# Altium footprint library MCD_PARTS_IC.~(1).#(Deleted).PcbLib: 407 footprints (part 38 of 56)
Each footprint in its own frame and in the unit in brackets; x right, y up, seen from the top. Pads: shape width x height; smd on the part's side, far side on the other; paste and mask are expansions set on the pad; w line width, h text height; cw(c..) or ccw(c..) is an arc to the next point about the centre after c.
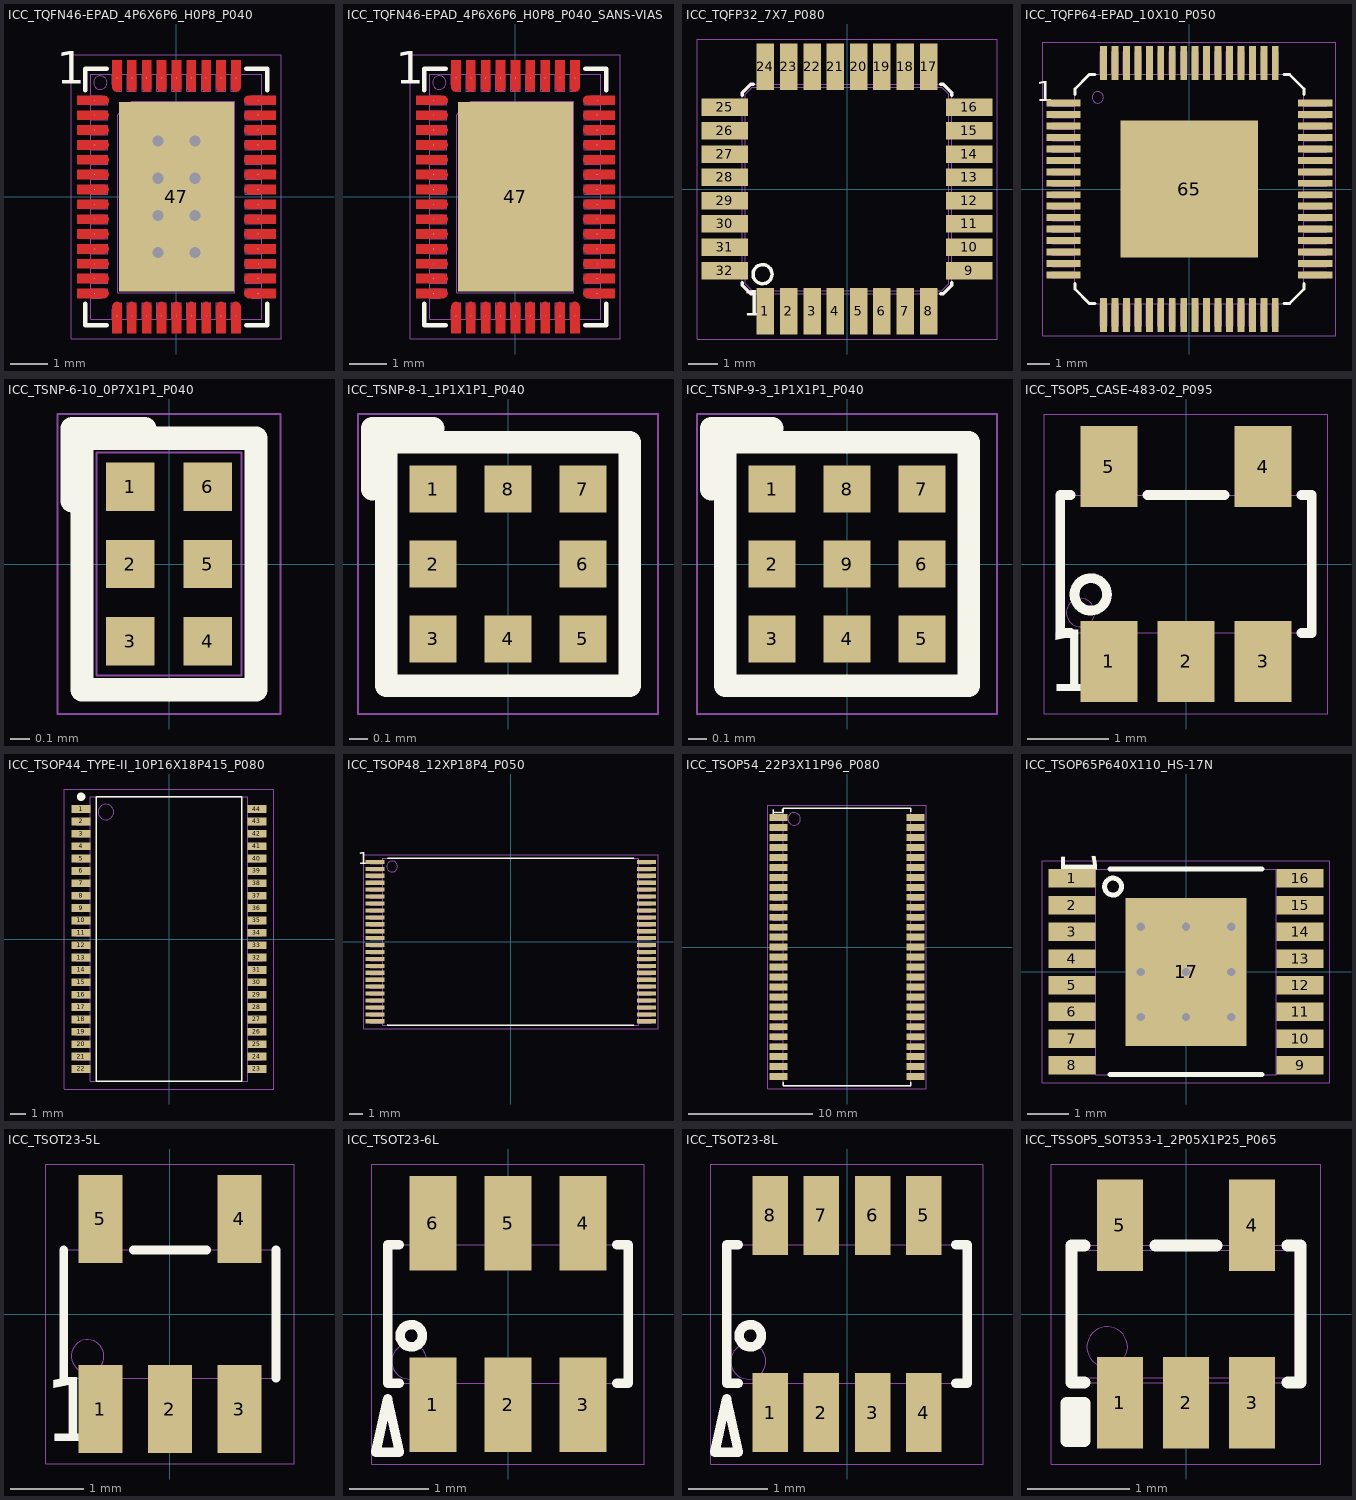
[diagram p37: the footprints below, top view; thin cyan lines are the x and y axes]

## ICC_TQFN46-EPAD_4P6X6P6_H0P8_P040 [mm]
height 0.8
pads (47):
  round 0.025 smd paste-2539.97 mask+0.035: 1(-2.2,2.6) 2(-2.2,2.2) 3(-2.2,1.8) 4(-2.2,1.4) 5(-2.2,1) 6(-2.2,0.6) 7(-2.2,0.2) 8(-2.2,-0.2) 9(-2.2,-0.6) 10(-2.2,-1) 11(-2.2,-1.4) 12(-2.2,-1.8) 13(-2.2,-2.2) 14(-2.2,-2.6) 15(-1.6,-3.2) 16(-1.2,-3.2) 17(-0.8,-3.2) 18(-0.4,-3.2) 19(0,-3.2) 20(0.4,-3.2) 21(0.8,-3.2) 22(1.2,-3.2) 23(1.6,-3.2) 24(2.2,-2.6) 25(2.2,-2.2) 26(2.2,-1.8) 27(2.2,-1.4) 28(2.2,-1) 29(2.2,-0.6) 30(2.2,-0.2) 31(2.2,0.2) 32(2.2,0.6) 33(2.2,1) 34(2.2,1.4) 35(2.2,1.8) 36(2.2,2.2) 37(2.2,2.6) 38(1.6,3.2) 39(1.2,3.2) 40(0.8,3.2) 41(0.4,3.2) 42(0,3.2) 43(-0.4,3.2) 44(-0.8,3.2) 45(-1.2,3.2) 46(-1.6,3.2)
  rect 3.1x5.1 smd paste-2539.97 mask+0.05: 47(0,0)
via 0.5,-1.5 diameter 0.55 hole 0.3
via 0.5,-0.5 diameter 0.55 hole 0.3
via -0.5,-1.5 diameter 0.55 hole 0.3
via -0.5,-0.5 diameter 0.55 hole 0.3
via -0.5,0.5 diameter 0.55 hole 0.3
via -0.5,1.5 diameter 0.55 hole 0.3
via 0.5,1.5 diameter 0.55 hole 0.3
via 0.5,0.5 diameter 0.55 hole 0.3
Top Layer:
  region: -1.6,2.825 -1.625,2.825 -1.671,2.844 -1.706,2.879 -1.725,2.925 -1.725,2.95 -1.725,3.675 -1.475,3.675 -1.475,2.95 -1.475,2.925 -1.494,2.879 -1.529,2.844 -1.575,2.825
  region: -1.2,2.825 -1.225,2.825 -1.271,2.844 -1.306,2.879 -1.325,2.925 -1.325,2.95 -1.325,3.675 -1.075,3.675 -1.075,2.95 -1.075,2.925 -1.094,2.879 -1.129,2.844 -1.175,2.825
  region: -0.8,2.825 -0.825,2.825 -0.871,2.844 -0.906,2.879 -0.925,2.925 -0.925,2.95 -0.925,3.675 -0.675,3.675 -0.675,2.95 -0.675,2.925 -0.694,2.879 -0.729,2.844 -0.775,2.825
  region: -0.4,2.825 -0.425,2.825 -0.471,2.844 -0.506,2.879 -0.525,2.925 -0.525,2.95 -0.525,3.675 -0.275,3.675 -0.275,2.95 -0.275,2.925 -0.294,2.879 -0.329,2.844 -0.375,2.825
  region: 0,2.825 -0.025,2.825 -0.071,2.844 -0.106,2.879 -0.125,2.925 -0.125,2.95 -0.125,3.675 0.125,3.675 0.125,2.95 0.125,2.925 0.106,2.879 0.071,2.844 0.025,2.825
  region: 0.4,2.825 0.375,2.825 0.329,2.844 0.294,2.879 0.275,2.925 0.275,2.95 0.275,3.675 0.525,3.675 0.525,2.95 0.525,2.925 0.506,2.879 0.471,2.844 0.425,2.825
  region: 1.6,2.825 1.625,2.825 1.671,2.844 1.706,2.879 1.725,2.925 1.725,2.95 1.725,3.675 1.475,3.675 1.475,2.95 1.475,2.925 1.494,2.879 1.529,2.844 1.575,2.825
  region: 0.8,2.825 0.775,2.825 0.729,2.844 0.694,2.879 0.675,2.925 0.675,2.95 0.675,3.675 0.925,3.675 0.925,2.95 0.925,2.925 0.906,2.879 0.871,2.844 0.825,2.825
  region: 1.2,2.825 1.175,2.825 1.129,2.844 1.094,2.879 1.075,2.925 1.075,2.95 1.075,3.675 1.325,3.675 1.325,2.95 1.325,2.925 1.306,2.879 1.271,2.844 1.225,2.825
  region: 1.6,-2.825 1.625,-2.825 1.671,-2.844 1.706,-2.879 1.725,-2.925 1.725,-2.95 1.725,-3.675 1.475,-3.675 1.475,-2.95 1.475,-2.925 1.494,-2.879 1.529,-2.844 1.575,-2.825
  region: 1.2,-2.825 1.225,-2.825 1.271,-2.844 1.306,-2.879 1.325,-2.925 1.325,-2.95 1.325,-3.675 1.075,-3.675 1.075,-2.95 1.075,-2.925 1.094,-2.879 1.129,-2.844 1.175,-2.825
  region: 0.8,-2.825 0.825,-2.825 0.871,-2.844 0.906,-2.879 0.925,-2.925 0.925,-2.95 0.925,-3.675 0.675,-3.675 0.675,-2.95 0.675,-2.925 0.694,-2.879 0.729,-2.844 0.775,-2.825
  region: 0.4,-2.825 0.425,-2.825 0.471,-2.844 0.506,-2.879 0.525,-2.925 0.525,-2.95 0.525,-3.675 0.275,-3.675 0.275,-2.95 0.275,-2.925 0.294,-2.879 0.329,-2.844 0.375,-2.825
  region: 0,-2.825 0.025,-2.825 0.071,-2.844 0.106,-2.879 0.125,-2.925 0.125,-2.95 0.125,-3.675 -0.125,-3.675 -0.125,-2.95 -0.125,-2.925 -0.106,-2.879 -0.071,-2.844 -0.025,-2.825
  region: -0.4,-2.825 -0.375,-2.825 -0.329,-2.844 -0.294,-2.879 -0.275,-2.925 -0.275,-2.95 -0.275,-3.675 -0.525,-3.675 -0.525,-2.95 -0.525,-2.925 -0.506,-2.879 -0.471,-2.844 -0.425,-2.825
  region: -1.6,-2.825 -1.625,-2.825 -1.671,-2.844 -1.706,-2.879 -1.725,-2.925 -1.725,-2.95 -1.725,-3.675 -1.475,-3.675 -1.475,-2.95 -1.475,-2.925 -1.494,-2.879 -1.529,-2.844 -1.575,-2.825
  region: -0.8,-2.825 -0.775,-2.825 -0.729,-2.844 -0.694,-2.879 -0.675,-2.925 -0.675,-2.95 -0.675,-3.675 -0.925,-3.675 -0.925,-2.95 -0.925,-2.925 -0.906,-2.879 -0.871,-2.844 -0.825,-2.825
  region: -1.2,-2.825 -1.175,-2.825 -1.129,-2.844 -1.094,-2.879 -1.075,-2.925 -1.075,-2.95 -1.075,-3.675 -1.325,-3.675 -1.325,-2.95 -1.325,-2.925 -1.306,-2.879 -1.271,-2.844 -1.225,-2.825
  region: 1.825,-2.6 1.825,-2.625 1.844,-2.671 1.879,-2.706 1.925,-2.725 1.95,-2.725 2.675,-2.725 2.675,-2.475 1.95,-2.475 1.925,-2.475 1.879,-2.494 1.844,-2.529 1.825,-2.575
  region: 1.825,-2.2 1.825,-2.225 1.844,-2.271 1.879,-2.306 1.925,-2.325 1.95,-2.325 2.675,-2.325 2.675,-2.075 1.95,-2.075 1.925,-2.075 1.879,-2.094 1.844,-2.129 1.825,-2.175
  region: 1.825,-1.8 1.825,-1.825 1.844,-1.871 1.879,-1.906 1.925,-1.925 1.95,-1.925 2.675,-1.925 2.675,-1.675 1.95,-1.675 1.925,-1.675 1.879,-1.694 1.844,-1.729 1.825,-1.775
  region: 1.825,-1.4 1.825,-1.425 1.844,-1.471 1.879,-1.506 1.925,-1.525 1.95,-1.525 2.675,-1.525 2.675,-1.275 1.95,-1.275 1.925,-1.275 1.879,-1.294 1.844,-1.329 1.825,-1.375
  region: 1.825,-1 1.825,-1.025 1.844,-1.071 1.879,-1.106 1.925,-1.125 1.95,-1.125 2.675,-1.125 2.675,-0.875 1.95,-0.875 1.925,-0.875 1.879,-0.894 1.844,-0.929 1.825,-0.975
  region: 1.825,-0.6 1.825,-0.625 1.844,-0.671 1.879,-0.706 1.925,-0.725 1.95,-0.725 2.675,-0.725 2.675,-0.475 1.95,-0.475 1.925,-0.475 1.879,-0.494 1.844,-0.529 1.825,-0.575
  region: 1.825,-0.2 1.825,-0.225 1.844,-0.271 1.879,-0.306 1.925,-0.325 1.95,-0.325 2.675,-0.325 2.675,-0.075 1.95,-0.075 1.925,-0.075 1.879,-0.094 1.844,-0.129 1.825,-0.175
  region: 1.825,0.2 1.825,0.175 1.844,0.129 1.879,0.094 1.925,0.075 1.95,0.075 2.675,0.075 2.675,0.325 1.95,0.325 1.925,0.325 1.879,0.306 1.844,0.271 1.825,0.225
  region: 1.825,0.6 1.825,0.575 1.844,0.529 1.879,0.494 1.925,0.475 1.95,0.475 2.675,0.475 2.675,0.725 1.95,0.725 1.925,0.725 1.879,0.706 1.844,0.671 1.825,0.625
  region: 1.825,1 1.825,0.975 1.844,0.929 1.879,0.894 1.925,0.875 1.95,0.875 2.675,0.875 2.675,1.125 1.95,1.125 1.925,1.125 1.879,1.106 1.844,1.071 1.825,1.025
  region: 1.825,1.4 1.825,1.375 1.844,1.329 1.879,1.294 1.925,1.275 1.95,1.275 2.675,1.275 2.675,1.525 1.95,1.525 1.925,1.525 1.879,1.506 1.844,1.471 1.825,1.425
  region: 1.825,2.6 1.825,2.575 1.844,2.529 1.879,2.494 1.925,2.475 1.95,2.475 2.675,2.475 2.675,2.725 1.95,2.725 1.925,2.725 1.879,2.706 1.844,2.671 1.825,2.625
  region: 1.825,1.8 1.825,1.775 1.844,1.729 1.879,1.694 1.925,1.675 1.95,1.675 2.675,1.675 2.675,1.925 1.95,1.925 1.925,1.925 1.879,1.906 1.844,1.871 1.825,1.825
  region: 1.825,2.2 1.825,2.175 1.844,2.129 1.879,2.094 1.925,2.075 1.95,2.075 2.675,2.075 2.675,2.325 1.95,2.325 1.925,2.325 1.879,2.306 1.844,2.271 1.825,2.225
  region: -1.825,-2.6 -1.825,-2.625 -1.844,-2.671 -1.879,-2.706 -1.925,-2.725 -1.95,-2.725 -2.675,-2.725 -2.675,-2.475 -1.95,-2.475 -1.925,-2.475 -1.879,-2.494 -1.844,-2.529 -1.825,-2.575
  region: -1.825,-2.2 -1.825,-2.225 -1.844,-2.271 -1.879,-2.306 -1.925,-2.325 -1.95,-2.325 -2.675,-2.325 -2.675,-2.075 -1.95,-2.075 -1.925,-2.075 -1.879,-2.094 -1.844,-2.129 -1.825,-2.175
  region: -1.825,-1.8 -1.825,-1.825 -1.844,-1.871 -1.879,-1.906 -1.925,-1.925 -1.95,-1.925 -2.675,-1.925 -2.675,-1.675 -1.95,-1.675 -1.925,-1.675 -1.879,-1.694 -1.844,-1.729 -1.825,-1.775
  region: -1.825,-1.4 -1.825,-1.425 -1.844,-1.471 -1.879,-1.506 -1.925,-1.525 -1.95,-1.525 -2.675,-1.525 -2.675,-1.275 -1.95,-1.275 -1.925,-1.275 -1.879,-1.294 -1.844,-1.329 -1.825,-1.375
  region: -1.825,-1 -1.825,-1.025 -1.844,-1.071 -1.879,-1.106 -1.925,-1.125 -1.95,-1.125 -2.675,-1.125 -2.675,-0.875 -1.95,-0.875 -1.925,-0.875 -1.879,-0.894 -1.844,-0.929 -1.825,-0.975
  region: -1.825,-0.6 -1.825,-0.625 -1.844,-0.671 -1.879,-0.706 -1.925,-0.725 -1.95,-0.725 -2.675,-0.725 -2.675,-0.475 -1.95,-0.475 -1.925,-0.475 -1.879,-0.494 -1.844,-0.529 -1.825,-0.575
  region: -1.825,-0.2 -1.825,-0.225 -1.844,-0.271 -1.879,-0.306 -1.925,-0.325 -1.95,-0.325 -2.675,-0.325 -2.675,-0.075 -1.95,-0.075 -1.925,-0.075 -1.879,-0.094 -1.844,-0.129 -1.825,-0.175
  region: -1.825,0.2 -1.825,0.175 -1.844,0.129 -1.879,0.094 -1.925,0.075 -1.95,0.075 -2.675,0.075 -2.675,0.325 -1.95,0.325 -1.925,0.325 -1.879,0.306 -1.844,0.271 -1.825,0.225
  region: -1.825,0.6 -1.825,0.575 -1.844,0.529 -1.879,0.494 -1.925,0.475 -1.95,0.475 -2.675,0.475 -2.675,0.725 -1.95,0.725 -1.925,0.725 -1.879,0.706 -1.844,0.671 -1.825,0.625
  region: -1.825,1 -1.825,0.975 -1.844,0.929 -1.879,0.894 -1.925,0.875 -1.95,0.875 -2.675,0.875 -2.675,1.125 -1.95,1.125 -1.925,1.125 -1.879,1.106 -1.844,1.071 -1.825,1.025
  region: -1.825,1.4 -1.825,1.375 -1.844,1.329 -1.879,1.294 -1.925,1.275 -1.95,1.275 -2.675,1.275 -2.675,1.525 -1.95,1.525 -1.925,1.525 -1.879,1.506 -1.844,1.471 -1.825,1.425
  region: -1.825,2.6 -1.825,2.575 -1.844,2.529 -1.879,2.494 -1.925,2.475 -1.95,2.475 -2.675,2.475 -2.675,2.725 -1.95,2.725 -1.925,2.725 -1.879,2.706 -1.844,2.671 -1.825,2.625
  region: -1.825,1.8 -1.825,1.775 -1.844,1.729 -1.879,1.694 -1.925,1.675 -1.95,1.675 -2.675,1.675 -2.675,1.925 -1.95,1.925 -1.925,1.925 -1.879,1.906 -1.844,1.871 -1.825,1.825
  region: -1.825,2.2 -1.825,2.175 -1.844,2.129 -1.879,2.094 -1.925,2.075 -1.95,2.075 -2.675,2.075 -2.675,2.325 -1.95,2.325 -1.925,2.325 -1.879,2.306 -1.844,2.271 -1.825,2.225
Top Overlay:
  lines w0.12: -2.45,-2.875 -2.45,-3.45 -1.875,-3.45 ; -2.45,2.875 -2.45,3.45 -1.875,3.45 ; 1.875,-3.45 2.45,-3.45 2.45,-2.875 ; 1.875,3.45 2.45,3.45 2.45,2.875
  text "1" at -3.225,2.75 h1.5
Top Paste:
  drawing of 52 lines, arcs and shapes, not listed
M14-Top Assembly:
  drawing of 164 lines, arcs and shapes, not listed
  text "'.Designator'" at -2,-0.5 h0.75
M16-Top Courtyard:
  lines w0.01: -2.825,-3.825 2.825,-3.825 2.825,3.825 -2.825,3.825 -2.825,-3.825
3D body: height 0.8, standoff 0, extent -2.3,-3.3 2.3,3.3
3D body: height 0.81, standoff 0.8, extent -2.006,2.616 -1.606,3.016

## ICC_TQFN46-EPAD_4P6X6P6_H0P8_P040_SANS-VIAS [mm]
height 0.8
pads (47):
  round 0.025 smd paste-2539.97 mask+0.035: 1(-2.2,2.6) 2(-2.2,2.2) 3(-2.2,1.8) 4(-2.2,1.4) 5(-2.2,1) 6(-2.2,0.6) 7(-2.2,0.2) 8(-2.2,-0.2) 9(-2.2,-0.6) 10(-2.2,-1) 11(-2.2,-1.4) 12(-2.2,-1.8) 13(-2.2,-2.2) 14(-2.2,-2.6) 15(-1.6,-3.2) 16(-1.2,-3.2) 17(-0.8,-3.2) 18(-0.4,-3.2) 19(0,-3.2) 20(0.4,-3.2) 21(0.8,-3.2) 22(1.2,-3.2) 23(1.6,-3.2) 24(2.2,-2.6) 25(2.2,-2.2) 26(2.2,-1.8) 27(2.2,-1.4) 28(2.2,-1) 29(2.2,-0.6) 30(2.2,-0.2) 31(2.2,0.2) 32(2.2,0.6) 33(2.2,1) 34(2.2,1.4) 35(2.2,1.8) 36(2.2,2.2) 37(2.2,2.6) 38(1.6,3.2) 39(1.2,3.2) 40(0.8,3.2) 41(0.4,3.2) 42(0,3.2) 43(-0.4,3.2) 44(-0.8,3.2) 45(-1.2,3.2) 46(-1.6,3.2)
  rect 3.1x5.1 smd paste-2539.97 mask+0.05: 47(0,0)
Top Layer:
  region: -1.825,2.2 -1.825,2.175 -1.844,2.129 -1.879,2.094 -1.925,2.075 -1.95,2.075 -2.675,2.075 -2.675,2.325 -1.95,2.325 -1.925,2.325 -1.879,2.306 -1.844,2.271 -1.825,2.225
  region: -1.825,1.8 -1.825,1.775 -1.844,1.729 -1.879,1.694 -1.925,1.675 -1.95,1.675 -2.675,1.675 -2.675,1.925 -1.95,1.925 -1.925,1.925 -1.879,1.906 -1.844,1.871 -1.825,1.825
  region: -1.825,2.6 -1.825,2.575 -1.844,2.529 -1.879,2.494 -1.925,2.475 -1.95,2.475 -2.675,2.475 -2.675,2.725 -1.95,2.725 -1.925,2.725 -1.879,2.706 -1.844,2.671 -1.825,2.625
  region: -1.825,1.4 -1.825,1.375 -1.844,1.329 -1.879,1.294 -1.925,1.275 -1.95,1.275 -2.675,1.275 -2.675,1.525 -1.95,1.525 -1.925,1.525 -1.879,1.506 -1.844,1.471 -1.825,1.425
  region: -1.825,1 -1.825,0.975 -1.844,0.929 -1.879,0.894 -1.925,0.875 -1.95,0.875 -2.675,0.875 -2.675,1.125 -1.95,1.125 -1.925,1.125 -1.879,1.106 -1.844,1.071 -1.825,1.025
  region: -1.825,0.6 -1.825,0.575 -1.844,0.529 -1.879,0.494 -1.925,0.475 -1.95,0.475 -2.675,0.475 -2.675,0.725 -1.95,0.725 -1.925,0.725 -1.879,0.706 -1.844,0.671 -1.825,0.625
  region: -1.825,0.2 -1.825,0.175 -1.844,0.129 -1.879,0.094 -1.925,0.075 -1.95,0.075 -2.675,0.075 -2.675,0.325 -1.95,0.325 -1.925,0.325 -1.879,0.306 -1.844,0.271 -1.825,0.225
  region: -1.825,-0.2 -1.825,-0.225 -1.844,-0.271 -1.879,-0.306 -1.925,-0.325 -1.95,-0.325 -2.675,-0.325 -2.675,-0.075 -1.95,-0.075 -1.925,-0.075 -1.879,-0.094 -1.844,-0.129 -1.825,-0.175
  region: -1.825,-0.6 -1.825,-0.625 -1.844,-0.671 -1.879,-0.706 -1.925,-0.725 -1.95,-0.725 -2.675,-0.725 -2.675,-0.475 -1.95,-0.475 -1.925,-0.475 -1.879,-0.494 -1.844,-0.529 -1.825,-0.575
  region: -1.825,-1 -1.825,-1.025 -1.844,-1.071 -1.879,-1.106 -1.925,-1.125 -1.95,-1.125 -2.675,-1.125 -2.675,-0.875 -1.95,-0.875 -1.925,-0.875 -1.879,-0.894 -1.844,-0.929 -1.825,-0.975
  region: -1.825,-1.4 -1.825,-1.425 -1.844,-1.471 -1.879,-1.506 -1.925,-1.525 -1.95,-1.525 -2.675,-1.525 -2.675,-1.275 -1.95,-1.275 -1.925,-1.275 -1.879,-1.294 -1.844,-1.329 -1.825,-1.375
  region: -1.825,-1.8 -1.825,-1.825 -1.844,-1.871 -1.879,-1.906 -1.925,-1.925 -1.95,-1.925 -2.675,-1.925 -2.675,-1.675 -1.95,-1.675 -1.925,-1.675 -1.879,-1.694 -1.844,-1.729 -1.825,-1.775
  region: -1.825,-2.2 -1.825,-2.225 -1.844,-2.271 -1.879,-2.306 -1.925,-2.325 -1.95,-2.325 -2.675,-2.325 -2.675,-2.075 -1.95,-2.075 -1.925,-2.075 -1.879,-2.094 -1.844,-2.129 -1.825,-2.175
  region: -1.825,-2.6 -1.825,-2.625 -1.844,-2.671 -1.879,-2.706 -1.925,-2.725 -1.95,-2.725 -2.675,-2.725 -2.675,-2.475 -1.95,-2.475 -1.925,-2.475 -1.879,-2.494 -1.844,-2.529 -1.825,-2.575
  region: 1.825,2.2 1.825,2.175 1.844,2.129 1.879,2.094 1.925,2.075 1.95,2.075 2.675,2.075 2.675,2.325 1.95,2.325 1.925,2.325 1.879,2.306 1.844,2.271 1.825,2.225
  region: 1.825,1.8 1.825,1.775 1.844,1.729 1.879,1.694 1.925,1.675 1.95,1.675 2.675,1.675 2.675,1.925 1.95,1.925 1.925,1.925 1.879,1.906 1.844,1.871 1.825,1.825
  region: 1.825,2.6 1.825,2.575 1.844,2.529 1.879,2.494 1.925,2.475 1.95,2.475 2.675,2.475 2.675,2.725 1.95,2.725 1.925,2.725 1.879,2.706 1.844,2.671 1.825,2.625
  region: 1.825,1.4 1.825,1.375 1.844,1.329 1.879,1.294 1.925,1.275 1.95,1.275 2.675,1.275 2.675,1.525 1.95,1.525 1.925,1.525 1.879,1.506 1.844,1.471 1.825,1.425
  region: 1.825,1 1.825,0.975 1.844,0.929 1.879,0.894 1.925,0.875 1.95,0.875 2.675,0.875 2.675,1.125 1.95,1.125 1.925,1.125 1.879,1.106 1.844,1.071 1.825,1.025
  region: 1.825,0.6 1.825,0.575 1.844,0.529 1.879,0.494 1.925,0.475 1.95,0.475 2.675,0.475 2.675,0.725 1.95,0.725 1.925,0.725 1.879,0.706 1.844,0.671 1.825,0.625
  region: 1.825,0.2 1.825,0.175 1.844,0.129 1.879,0.094 1.925,0.075 1.95,0.075 2.675,0.075 2.675,0.325 1.95,0.325 1.925,0.325 1.879,0.306 1.844,0.271 1.825,0.225
  region: 1.825,-0.2 1.825,-0.225 1.844,-0.271 1.879,-0.306 1.925,-0.325 1.95,-0.325 2.675,-0.325 2.675,-0.075 1.95,-0.075 1.925,-0.075 1.879,-0.094 1.844,-0.129 1.825,-0.175
  region: 1.825,-0.6 1.825,-0.625 1.844,-0.671 1.879,-0.706 1.925,-0.725 1.95,-0.725 2.675,-0.725 2.675,-0.475 1.95,-0.475 1.925,-0.475 1.879,-0.494 1.844,-0.529 1.825,-0.575
  region: 1.825,-1 1.825,-1.025 1.844,-1.071 1.879,-1.106 1.925,-1.125 1.95,-1.125 2.675,-1.125 2.675,-0.875 1.95,-0.875 1.925,-0.875 1.879,-0.894 1.844,-0.929 1.825,-0.975
  region: 1.825,-1.4 1.825,-1.425 1.844,-1.471 1.879,-1.506 1.925,-1.525 1.95,-1.525 2.675,-1.525 2.675,-1.275 1.95,-1.275 1.925,-1.275 1.879,-1.294 1.844,-1.329 1.825,-1.375
  region: 1.825,-1.8 1.825,-1.825 1.844,-1.871 1.879,-1.906 1.925,-1.925 1.95,-1.925 2.675,-1.925 2.675,-1.675 1.95,-1.675 1.925,-1.675 1.879,-1.694 1.844,-1.729 1.825,-1.775
  region: 1.825,-2.2 1.825,-2.225 1.844,-2.271 1.879,-2.306 1.925,-2.325 1.95,-2.325 2.675,-2.325 2.675,-2.075 1.95,-2.075 1.925,-2.075 1.879,-2.094 1.844,-2.129 1.825,-2.175
  region: 1.825,-2.6 1.825,-2.625 1.844,-2.671 1.879,-2.706 1.925,-2.725 1.95,-2.725 2.675,-2.725 2.675,-2.475 1.95,-2.475 1.925,-2.475 1.879,-2.494 1.844,-2.529 1.825,-2.575
  region: -1.2,-2.825 -1.175,-2.825 -1.129,-2.844 -1.094,-2.879 -1.075,-2.925 -1.075,-2.95 -1.075,-3.675 -1.325,-3.675 -1.325,-2.95 -1.325,-2.925 -1.306,-2.879 -1.271,-2.844 -1.225,-2.825
  region: -0.8,-2.825 -0.775,-2.825 -0.729,-2.844 -0.694,-2.879 -0.675,-2.925 -0.675,-2.95 -0.675,-3.675 -0.925,-3.675 -0.925,-2.95 -0.925,-2.925 -0.906,-2.879 -0.871,-2.844 -0.825,-2.825
  region: -1.6,-2.825 -1.625,-2.825 -1.671,-2.844 -1.706,-2.879 -1.725,-2.925 -1.725,-2.95 -1.725,-3.675 -1.475,-3.675 -1.475,-2.95 -1.475,-2.925 -1.494,-2.879 -1.529,-2.844 -1.575,-2.825
  region: -0.4,-2.825 -0.375,-2.825 -0.329,-2.844 -0.294,-2.879 -0.275,-2.925 -0.275,-2.95 -0.275,-3.675 -0.525,-3.675 -0.525,-2.95 -0.525,-2.925 -0.506,-2.879 -0.471,-2.844 -0.425,-2.825
  region: 0,-2.825 0.025,-2.825 0.071,-2.844 0.106,-2.879 0.125,-2.925 0.125,-2.95 0.125,-3.675 -0.125,-3.675 -0.125,-2.95 -0.125,-2.925 -0.106,-2.879 -0.071,-2.844 -0.025,-2.825
  region: 0.4,-2.825 0.425,-2.825 0.471,-2.844 0.506,-2.879 0.525,-2.925 0.525,-2.95 0.525,-3.675 0.275,-3.675 0.275,-2.95 0.275,-2.925 0.294,-2.879 0.329,-2.844 0.375,-2.825
  region: 0.8,-2.825 0.825,-2.825 0.871,-2.844 0.906,-2.879 0.925,-2.925 0.925,-2.95 0.925,-3.675 0.675,-3.675 0.675,-2.95 0.675,-2.925 0.694,-2.879 0.729,-2.844 0.775,-2.825
  region: 1.2,-2.825 1.225,-2.825 1.271,-2.844 1.306,-2.879 1.325,-2.925 1.325,-2.95 1.325,-3.675 1.075,-3.675 1.075,-2.95 1.075,-2.925 1.094,-2.879 1.129,-2.844 1.175,-2.825
  region: 1.6,-2.825 1.625,-2.825 1.671,-2.844 1.706,-2.879 1.725,-2.925 1.725,-2.95 1.725,-3.675 1.475,-3.675 1.475,-2.95 1.475,-2.925 1.494,-2.879 1.529,-2.844 1.575,-2.825
  region: 1.2,2.825 1.175,2.825 1.129,2.844 1.094,2.879 1.075,2.925 1.075,2.95 1.075,3.675 1.325,3.675 1.325,2.95 1.325,2.925 1.306,2.879 1.271,2.844 1.225,2.825
  region: 0.8,2.825 0.775,2.825 0.729,2.844 0.694,2.879 0.675,2.925 0.675,2.95 0.675,3.675 0.925,3.675 0.925,2.95 0.925,2.925 0.906,2.879 0.871,2.844 0.825,2.825
  region: 1.6,2.825 1.625,2.825 1.671,2.844 1.706,2.879 1.725,2.925 1.725,2.95 1.725,3.675 1.475,3.675 1.475,2.95 1.475,2.925 1.494,2.879 1.529,2.844 1.575,2.825
  region: 0.4,2.825 0.375,2.825 0.329,2.844 0.294,2.879 0.275,2.925 0.275,2.95 0.275,3.675 0.525,3.675 0.525,2.95 0.525,2.925 0.506,2.879 0.471,2.844 0.425,2.825
  region: 0,2.825 -0.025,2.825 -0.071,2.844 -0.106,2.879 -0.125,2.925 -0.125,2.95 -0.125,3.675 0.125,3.675 0.125,2.95 0.125,2.925 0.106,2.879 0.071,2.844 0.025,2.825
  region: -0.4,2.825 -0.425,2.825 -0.471,2.844 -0.506,2.879 -0.525,2.925 -0.525,2.95 -0.525,3.675 -0.275,3.675 -0.275,2.95 -0.275,2.925 -0.294,2.879 -0.329,2.844 -0.375,2.825
  region: -0.8,2.825 -0.825,2.825 -0.871,2.844 -0.906,2.879 -0.925,2.925 -0.925,2.95 -0.925,3.675 -0.675,3.675 -0.675,2.95 -0.675,2.925 -0.694,2.879 -0.729,2.844 -0.775,2.825
  region: -1.2,2.825 -1.225,2.825 -1.271,2.844 -1.306,2.879 -1.325,2.925 -1.325,2.95 -1.325,3.675 -1.075,3.675 -1.075,2.95 -1.075,2.925 -1.094,2.879 -1.129,2.844 -1.175,2.825
  region: -1.6,2.825 -1.625,2.825 -1.671,2.844 -1.706,2.879 -1.725,2.925 -1.725,2.95 -1.725,3.675 -1.475,3.675 -1.475,2.95 -1.475,2.925 -1.494,2.879 -1.529,2.844 -1.575,2.825
Top Overlay:
  lines w0.12: -2.45,-2.875 -2.45,-3.45 -1.875,-3.45 ; -2.45,2.875 -2.45,3.45 -1.875,3.45 ; 1.875,-3.45 2.45,-3.45 2.45,-2.875 ; 1.875,3.45 2.45,3.45 2.45,2.875
  text "1" at -3.225,2.75 h1.5
Top Paste:
  drawing of 52 lines, arcs and shapes, not listed
M14-Top Assembly:
  drawing of 164 lines, arcs and shapes, not listed
  text "'.Designator'" at -2,-0.5 h0.75
M16-Top Courtyard:
  lines w0.01: -2.825,-3.825 -2.825,3.825 2.825,3.825 2.825,-3.825 -2.825,-3.825
3D body: height 0.81, standoff 0.8, extent -2.006,2.616 -1.606,3.016
3D body: height 0.8, standoff 0, extent -2.3,-3.3 2.3,3.3

## ICC_TQFP32_7X7_P080 [mm] "MCD-01846"
height 1.6
pads (32):
  rect 0.6x1.6 smd mask+0.05: 1(-2.8,-4.2) 2(-2,-4.2) 3(-1.2,-4.2) 4(-0.4,-4.2) 5(0.4,-4.2) 6(1.2,-4.2) 7(2,-4.2) 8(2.8,-4.2) 17(2.8,4.2) 18(2,4.2) 19(1.2,4.2) 20(0.4,4.2) 21(-0.4,4.2) 22(-1.2,4.2) 23(-2,4.2) 24(-2.8,4.2)
  rect 1.6x0.6 smd mask+0.05: 9(4.2,-2.8) 10(4.2,-2) 11(4.2,-1.2) 12(4.2,-0.4) 13(4.2,0.4) 14(4.2,1.2) 15(4.2,2) 16(4.2,2.8) 25(-4.2,2.8) 26(-4.2,2) 27(-4.2,1.2) 28(-4.2,0.4) 29(-4.2,-0.4) 30(-4.2,-1.2) 31(-4.2,-2) 32(-4.2,-2.8)
Top Overlay:
  circle w0.12: c-2.9,-2.925 r0.326
  lines w0.12: -3.6,-3.225 -3.6,-3.3 -3.3,-3.6 -3.225,-3.6 ; -3.6,3.225 -3.6,3.3 -3.3,3.6 -3.225,3.6 ; 3.225,-3.6 3.3,-3.6 3.6,-3.3 3.6,-3.225 ; 3.225,3.6 3.3,3.6 3.6,3.3 3.6,3.225
  text "1" at -3.575,-4.65 h1.5
M14-Top Assembly:
  circle w0.01: c-2.9,-2.925 r0.335
  lines w0.01: -3.6,-3 -4.6,-3 -4.6,-2.6 -3.6,-2.6 ; -3.6,-2.2 -4.6,-2.2 -4.6,-1.8 -3.6,-1.8 ; -3.6,-1.4 -4.6,-1.4 -4.6,-1 -3.6,-1 ; -3.6,-0.6 -4.6,-0.6 -4.6,-0.2 -3.6,-0.2 ; -3.6,0.2 -4.6,0.2 -4.6,0.6 -3.6,0.6 ; -3.6,1 -4.6,1 -4.6,1.4 -3.6,1.4 ; -3.6,1.8 -4.6,1.8 -4.6,2.2 -3.6,2.2 ; -3.6,2.6 -4.6,2.6 -4.6,3 -3.6,3 ; -3,-3.6 -3,-4.6 -2.6,-4.6 -2.6,-3.6 ; -3,3.6 -3,4.6 -2.6,4.6 -2.6,3.6 ; -2.2,-3.6 -2.2,-4.6 -1.8,-4.6 -1.8,-3.6 ; -2.2,3.6 -2.2,4.6 -1.8,4.6 -1.8,3.6 ; -1.4,-3.6 -1.4,-4.6 -1,-4.6 -1,-3.6 ; -1.4,3.6 -1.4,4.6 -1,4.6 -1,3.6 ; -0.6,-3.6 -0.6,-4.6 -0.2,-4.6 -0.2,-3.6 ; -0.6,3.6 -0.6,4.6 -0.2,4.6 -0.2,3.6 ; 0.2,-3.6 0.2,-4.6 0.6,-4.6 0.6,-3.6 ; 0.2,3.6 0.2,4.6 0.6,4.6 0.6,3.6 ; 1,-3.6 1,-4.6 1.4,-4.6 1.4,-3.6 ; 1,3.6 1,4.6 1.4,4.6 1.4,3.6 ; 1.8,-3.6 1.8,-4.6 2.2,-4.6 2.2,-3.6 ; 1.8,3.6 1.8,4.6 2.2,4.6 2.2,3.6 ; 2.6,-3.6 2.6,-4.6 3,-4.6 3,-3.6 ; 2.6,3.6 2.6,4.6 3,4.6 3,3.6 ; 3.6,-3 4.6,-3 4.6,-2.6 3.6,-2.6 ; 3.6,-2.2 4.6,-2.2 4.6,-1.8 3.6,-1.8 ; 3.6,-1.4 4.6,-1.4 4.6,-1 3.6,-1 ; 3.6,-0.6 4.6,-0.6 4.6,-0.2 3.6,-0.2 ; 3.6,0.2 4.6,0.2 4.6,0.6 3.6,0.6 ; 3.6,1 4.6,1 4.6,1.4 3.6,1.4 ; 3.6,1.8 4.6,1.8 4.6,2.2 3.6,2.2 ; 3.6,2.6 4.6,2.6 4.6,3 3.6,3 ; -3.6,-3.3 -3.3,-3.6 3.3,-3.6 3.6,-3.3 3.6,3.3 3.3,3.6 -3.3,3.6 -3.6,3.3 -3.6,-3.3 ; -3.5,-3.25 -3.25,-3.5 3.25,-3.5 3.5,-3.25 3.5,3.25 3.25,3.5 -3.25,3.5 -3.5,3.25 -3.5,-3.25
  text "'.Designator'" at -2,-0.5 h0.75
  text "1" at -3.425,-4.625 h1.5
M16-Top Courtyard:
  lines w0.01: -5.15,-5.15 -5.15,5.15 5.15,5.15 5.15,-5.15 -5.15,-5.15
3D body: height 1.6, standoff 0, extent -3.585,-3.585 3.585,3.585
3D body "TQFP32-1.STEP": height 1.1, standoff 0, extent -4.509,-4.509 4.509,4.509

## ICC_TQFP64-EPAD_10X10_P050 [mm] "MCD-04238"
height 1.2
pads (65):
  rect 1.5x0.3 smd mask+0.05: 1(-5.5,3.75) 2(-5.5,3.25) 3(-5.5,2.75) 4(-5.5,2.25) 5(-5.5,1.75) 6(-5.5,1.25) 7(-5.5,0.75) 8(-5.5,0.25) 9(-5.5,-0.25) 10(-5.5,-0.75) 11(-5.5,-1.25) 12(-5.5,-1.75) 13(-5.5,-2.25) 14(-5.5,-2.75) 15(-5.5,-3.25) 16(-5.5,-3.75) 33(5.5,-3.75) 34(5.5,-3.25) 35(5.5,-2.75) 36(5.5,-2.25) 37(5.5,-1.75) 38(5.5,-1.25) 39(5.5,-0.75) 40(5.5,-0.25) 41(5.5,0.25) 42(5.5,0.75) 43(5.5,1.25) 44(5.5,1.75) 45(5.5,2.25) 46(5.5,2.75) 47(5.5,3.25) 48(5.5,3.75)
  rect 0.3x1.5 smd mask+0.05: 17(-3.75,-5.5) 18(-3.25,-5.5) 19(-2.75,-5.5) 20(-2.25,-5.5) 21(-1.75,-5.5) 22(-1.25,-5.5) 23(-0.75,-5.5) 24(-0.25,-5.5) 25(0.25,-5.5) 26(0.75,-5.5) 27(1.25,-5.5) 28(1.75,-5.5) 29(2.25,-5.5) 30(2.75,-5.5) 31(3.25,-5.5) 32(3.75,-5.5) 49(3.75,5.5) 50(3.25,5.5) 51(2.75,5.5) 52(2.25,5.5) 53(1.75,5.5) 54(1.25,5.5) 55(0.75,5.5) 56(0.25,5.5) 57(-0.25,5.5) 58(-0.75,5.5) 59(-1.25,5.5) 60(-1.75,5.5) 61(-2.25,5.5) 62(-2.75,5.5) 63(-3.25,5.5) 64(-3.75,5.5)
  rect 6x6 smd mask+0.05: 65(0,0)
Top Overlay:
  lines w0.12: -5,-4.125 -5,-4.375 -4.375,-5 -4.125,-5 ; -5,4.125 -5,4.375 -4.375,5 -4.125,5 ; 4.125,-5 4.375,-5 5,-4.375 5,-4.125 ; 4.125,5 4.375,5 5,4.375 5,4.125
  text "1" at -6.7,3.525 h1.5
M14-Top Assembly:
  drawing of 269 lines, arcs and shapes, not listed
  text "'.Designator'" at -2,-0.5 h0.75
  text "1" at -6.7,3.525 h1.5
M16-Top Courtyard:
  lines w0.01: -6.4,-6.4 -6.4,6.4 6.4,6.4 6.4,-6.4 -6.4,-6.4
3D body "User Library-TQFP64_05.STEP": height 1.2, standoff 0, extent -6,-6 6,6

## ICC_TSNP-6-10_0P7X1P1_P040 [mm] "MCD-03680"
height 0.4
pads (6):
  rect 0.25x0.25 smd paste-10 mask+0.038: 1(-0.2,0.4) 2(-0.2,0) 3(-0.2,-0.4) 4(0.2,-0.4) 5(0.2,0) 6(0.2,0.4)
Top Overlay:
  lines w0.12: -0.5,0.325 -0.5,0.7 -0.125,0.7 ; -0.45,-0.65 0.45,-0.65 0.45,0.65 -0.45,0.65 -0.45,-0.65
Top Paste:
  circle w0.23: c-0.2,0.4 r0.01
  circle w0.23: c0.2,0.4 r0.01
  circle w0.23: c-0.2,0 r0.01
  circle w0.23: c0.2,0 r0.01
  circle w0.23: c-0.2,-0.4 r0.01
  circle w0.23: c0.2,-0.4 r0.01
M14-Top Assembly:
  lines w0.01: -0.375,-0.575 0.375,-0.575 0.375,0.575 -0.375,0.575 -0.375,-0.575 ; -0.3,-0.5 -0.1,-0.5 -0.1,-0.3 -0.3,-0.3 -0.3,-0.5 ; -0.3,-0.1 -0.1,-0.1 -0.1,0.1 -0.3,0.1 -0.3,-0.1 ; -0.3,0.3 -0.1,0.3 -0.1,0.5 -0.3,0.5 -0.3,0.3 ; 0.1,-0.5 0.3,-0.5 0.3,-0.3 0.1,-0.3 0.1,-0.5 ; 0.1,-0.1 0.3,-0.1 0.3,0.1 0.1,0.1 0.1,-0.1 ; 0.1,0.3 0.3,0.3 0.3,0.5 0.1,0.5 0.1,0.3
  text "'.Designator'" at -2,-0.5 h0.75
  text "1" at -0.229,0.319 h0.25
  text "2" at -0.253,-0.081 h0.25
  text "3" at -0.252,-0.479 h0.25
  text "4" at 0.145,-0.48 h0.25
  text "5" at 0.147,-0.078 h0.25
  text "6" at 0.147,0.321 h0.25
M16-Top Courtyard:
  lines w0.01: -0.575,-0.775 0.575,-0.775 0.575,0.775 -0.575,0.775 -0.575,-0.775
3D body: height 0.02, standoff 0, extent 0.1,0.3 0.3,0.5
3D body: height 0.02, standoff 0, extent -0.3,0.3 -0.1,0.5
3D body: height 0.02, standoff 0, extent -0.3,-0.1 -0.1,0.1
3D body: height 0.02, standoff 0, extent 0.1,-0.1 0.3,0.1
3D body: height 0.02, standoff 0, extent -0.3,-0.5 -0.1,-0.3
3D body: height 0.02, standoff 0, extent 0.1,-0.5 0.3,-0.3
3D body: height 0.4, standoff 0.02, extent -0.375,-0.575 0.375,0.575
3D body: height 0.41, standoff 0.4, extent -0.3,0.3 -0.1,0.5

## ICC_TSNP-8-1_1P1X1P1_P040 [mm] "MCD-01478"
height 0.4
pads (8):
  rect 0.25x0.25 smd mask+0.038: 1(-0.4,0.4) 2(-0.4,0) 3(-0.4,-0.4) 4(0,-0.4) 5(0.4,-0.4) 6(0.4,0) 7(0.4,0.4) 8(0,0.4)
Top Overlay:
  lines w0.12: -0.725,0.4 -0.725,0.725 -0.4,0.725 ; -0.65,-0.65 0.65,-0.65 0.65,0.65 -0.65,0.65 -0.65,-0.65
M14-Top Assembly:
  lines w0.01: -0.6,-0.6 0.6,-0.6 0.6,0.6 -0.6,0.6 -0.6,-0.6 ; -0.5,-0.5 -0.5,-0.3 -0.3,-0.3 -0.3,-0.5 -0.5,-0.5 ; -0.5,-0.1 -0.5,0.1 -0.3,0.1 -0.3,-0.1 -0.5,-0.1 ; -0.5,0.3 -0.3,0.3 -0.3,0.5 -0.5,0.5 -0.5,0.3 ; -0.1,-0.5 -0.1,-0.3 0.1,-0.3 0.1,-0.5 -0.1,-0.5 ; -0.1,0.3 -0.1,0.5 0.1,0.5 0.1,0.3 -0.1,0.3 ; 0.3,-0.5 0.3,-0.3 0.5,-0.3 0.5,-0.5 0.3,-0.5 ; 0.3,-0.1 0.3,0.1 0.5,0.1 0.5,-0.1 0.3,-0.1 ; 0.3,0.3 0.3,0.5 0.5,0.5 0.5,0.3 0.3,0.3
  text "8" at -0.05,0.312 h0.25
  text "7" at 0.35,0.312 h0.25
  text "6" at 0.35,-0.088 h0.25
  text "5" at 0.35,-0.487 h0.25
  text "4" at -0.062,-0.487 h0.25
  text "3" at -0.45,-0.487 h0.25
  text "2" at -0.45,-0.088 h0.25
  text "1" at -0.437,0.312 h0.25
  text "'.Designator'" at -2,-0.5 h0.75
M16-Top Courtyard:
  lines w0.01: -0.8,-0.8 -0.8,0.8 0.8,0.8 0.8,-0.8 -0.8,-0.8
3D body: height 0.02, standoff 0, extent -0.5,0.3 -0.3,0.5
3D body: height 0.02, standoff 0, extent -0.1,0.3 0.1,0.5
3D body: height 0.02, standoff 0, extent 0.3,0.3 0.5,0.5
3D body: height 0.02, standoff 0, extent -0.5,-0.1 -0.3,0.1
3D body: height 0.02, standoff 0, extent -0.5,-0.5 -0.3,-0.3
3D body: height 0.02, standoff 0, extent -0.1,-0.5 0.1,-0.3
3D body: height 0.02, standoff 0, extent 0.3,-0.5 0.5,-0.3
3D body: height 0.02, standoff 0, extent 0.3,-0.1 0.5,0.1
3D body: height 0.4, standoff 0.02, extent -0.6,-0.6 0.6,0.6
3D body: height 0.41, standoff 0.4, extent -0.5,0.3 -0.3,0.5

## ICC_TSNP-9-3_1P1X1P1_P040 [mm] "MCD-02018"
height 0.4
pads (9):
  rect 0.25x0.25 smd mask+0.038: 1(-0.4,0.4) 2(-0.4,0) 3(-0.4,-0.4) 4(0,-0.4) 5(0.4,-0.4) 6(0.4,0) 7(0.4,0.4) 8(0,0.4) 9(0,0)
Top Overlay:
  lines w0.12: -0.725,0.4 -0.725,0.725 -0.4,0.725 ; -0.65,-0.65 0.65,-0.65 0.65,0.65 -0.65,0.65 -0.65,-0.65
M14-Top Assembly:
  lines w0.01: -0.6,-0.6 0.6,-0.6 0.6,0.6 -0.6,0.6 -0.6,-0.6 ; -0.5,-0.5 -0.5,-0.3 -0.3,-0.3 -0.3,-0.5 -0.5,-0.5 ; -0.5,-0.1 -0.5,0.1 -0.3,0.1 -0.3,-0.1 -0.5,-0.1 ; -0.5,0.3 -0.3,0.3 -0.3,0.5 -0.5,0.5 -0.5,0.3 ; -0.1,-0.5 -0.1,-0.3 0.1,-0.3 0.1,-0.5 -0.1,-0.5 ; -0.1,-0.1 0.1,-0.1 0.1,0.1 -0.1,0.1 -0.1,-0.1 ; -0.1,0.3 -0.1,0.5 0.1,0.5 0.1,0.3 -0.1,0.3 ; 0.3,-0.5 0.3,-0.3 0.5,-0.3 0.5,-0.5 0.3,-0.5 ; 0.3,-0.1 0.3,0.1 0.5,0.1 0.5,-0.1 0.3,-0.1 ; 0.3,0.3 0.3,0.5 0.5,0.5 0.5,0.3 0.3,0.3
  text "9" at -0.05,-0.088 h0.25
  text "8" at -0.05,0.312 h0.25
  text "7" at 0.35,0.312 h0.25
  text "6" at 0.35,-0.088 h0.25
  text "5" at 0.35,-0.487 h0.25
  text "4" at -0.062,-0.487 h0.25
  text "3" at -0.45,-0.487 h0.25
  text "2" at -0.45,-0.088 h0.25
  text "1" at -0.437,0.312 h0.25
  text "'.Designator'" at -2,-0.5 h0.75
M16-Top Courtyard:
  lines w0.01: -0.8,-0.8 -0.8,0.8 0.8,0.8 0.8,-0.8 -0.8,-0.8
3D body: height 0.02, standoff 0, extent -0.5,0.3 -0.3,0.5
3D body: height 0.02, standoff 0, extent -0.1,0.3 0.1,0.5
3D body: height 0.02, standoff 0, extent 0.3,0.3 0.5,0.5
3D body: height 0.02, standoff 0, extent -0.5,-0.1 -0.3,0.1
3D body: height 0.02, standoff 0, extent -0.5,-0.5 -0.3,-0.3
3D body: height 0.02, standoff 0, extent -0.1,-0.5 0.1,-0.3
3D body: height 0.02, standoff 0, extent 0.3,-0.5 0.5,-0.3
3D body: height 0.02, standoff 0, extent 0.3,-0.1 0.5,0.1
3D body: height 0.4, standoff 0.02, extent -0.6,-0.6 0.6,0.6
3D body: height 0.41, standoff 0.4, extent -0.5,0.3 -0.3,0.5
3D body: height 0.02, standoff 0, extent -0.1,-0.1 0.1,0.1

## ICC_TSOP5_CASE-483-02_P095 [mm] "MCD-01515"
height 1.1
pads (5):
  rect 0.7x1 smd mask+0.05: 1(-0.95,-1.2) 2(0,-1.2) 3(0.95,-1.2) 4(0.95,1.2) 5(-0.95,1.2)
Top Overlay:
  circle w0.12: c-1.175,-0.375 r0.2
  lines w0.12: -1.425,-0.85 -1.55,-0.85 -1.55,0.85 -1.425,0.85 ; -0.475,0.85 0.475,0.85 ; 1.425,-0.85 1.55,-0.85 1.55,0.85 1.425,0.85
  text "1" at -1.725,-1.825 h1.3
M14-Top Assembly:
  circle w0.01: c-1.3,-0.6 r0.175
  lines w0.01: -1.2,-0.85 -1.2,-1.5 -0.7,-1.5 -0.7,-0.85 ; -1.2,0.85 -1.2,1.5 -0.7,1.5 -0.7,0.85 ; -0.25,-0.85 -0.25,-1.5 0.25,-1.5 0.25,-0.85 ; 0.7,-0.85 0.7,-1.5 1.2,-1.5 1.2,-0.85 ; 0.7,0.85 0.7,1.5 1.2,1.5 1.2,0.85 ; -1.55,-0.85 -1.55,0.85 1.55,0.85 1.55,-0.85 -1.55,-0.85
  text "5" at -1.125,0.925 h0.8
  text "4" at 0.775,0.925 h0.8
  text "'.Designator'" at -2,-0.5 h0.75
  text "1" at -1.075,-1.45 h0.8
  text "2" at -0.175,-1.45 h0.8
  text "3" at 0.775,-1.45 h0.8
M16-Top Courtyard:
  lines w0.01: -1.75,-1.85 -1.75,1.85 1.75,1.85 1.75,-1.85 -1.75,-1.85
3D body: height 1.1, standoff 0, extent -1.55,-0.85 1.55,0.85
3D body "5-TSOP.STEP": height 1.1, standoff 0, extent -1.55,-1.5 1.55,1.5

## ICC_TSOP44_TYPE-II_10P16X18P415_P080 [mm] "MCD-04319"
height 1.194
pads (44):
  rect 1.21x0.5 smd paste+0 mask+0.05: 1(-5.685,8.4) 2(-5.685,7.6) 3(-5.685,6.8) 4(-5.685,6) 5(-5.685,5.2) 6(-5.685,4.4) 7(-5.685,3.6) 8(-5.685,2.8) 9(-5.685,2) 10(-5.685,1.2) 11(-5.685,0.4) 12(-5.685,-0.4) 13(-5.685,-1.2) 14(-5.685,-2) 15(-5.685,-2.8) 16(-5.685,-3.6) 17(-5.685,-4.4) 18(-5.685,-5.2) 19(-5.685,-6) 20(-5.685,-6.8) 21(-5.685,-7.6) 22(-5.685,-8.4) 23(5.685,-8.4) 24(5.685,-7.6) 25(5.685,-6.8) 26(5.685,-6) 27(5.685,-5.2) 28(5.685,-4.4) 29(5.685,-3.6) 30(5.685,-2.8) 31(5.685,-2) 32(5.685,-1.2) 33(5.685,-0.4) 34(5.685,0.4) 35(5.685,1.2) 36(5.685,2) 37(5.685,2.8) 38(5.685,3.6) 39(5.685,4.4) 40(5.685,5.2) 41(5.685,6) 42(5.685,6.8) 43(5.685,7.6) 44(5.685,8.4)
Top Overlay:
  circle w0.3: c-5.685,9.2 r0.125
  lines w0.12: -4.7,-9.2 -4.7,9.2 4.7,9.2 4.7,-9.2 -4.7,-9.2
M14-Top Assembly:
  drawing of 181 lines, arcs and shapes, not listed
  text "'.Designator'" at -2,-0.5 h0.75
  text "1" at -5.862,7.918 h1.5
  text "22" at -6.378,-8.882 h1.5
  text "44" at 4.979,7.92 h1.5
  text "23" at 4.987,-8.874 h1.5
M16-Top Courtyard:
  lines w0.01: -6.79,-9.7 -6.79,9.7 6.79,9.7 6.79,-9.7 -6.79,-9.7
3D body "PG-TSOP-44-801_51-85087_V0F_3D.stp": height 1.2, standoff 0, extent -5.918,-9.207 5.918,9.208

## ICC_TSOP48_12XP18P4_P050 [mm] "MCD-04361"
height 1.2
pads (48):
  rect 1.35x0.3 smd mask+0.05: 1(-9.8,5.75) 2(-9.8,5.25) 3(-9.8,4.75) 4(-9.8,4.25) 5(-9.8,3.75) 6(-9.8,3.25) 7(-9.8,2.75) 8(-9.8,2.25) 9(-9.8,1.75) 10(-9.8,1.25) 11(-9.8,0.75) 12(-9.8,0.25) 13(-9.8,-0.25) 14(-9.8,-0.75) 15(-9.8,-1.25) 16(-9.8,-1.75) 17(-9.8,-2.25) 18(-9.8,-2.75) 19(-9.8,-3.25) 20(-9.8,-3.75) 21(-9.8,-4.25) 22(-9.8,-4.75) 23(-9.8,-5.25) 24(-9.8,-5.75) 25(9.8,-5.75) 26(9.8,-5.25) 27(9.8,-4.75) 28(9.8,-4.25) 29(9.8,-3.75) 30(9.8,-3.25) 31(9.8,-2.75) 32(9.8,-2.25) 33(9.8,-1.75) 34(9.8,-1.25) 35(9.8,-0.75) 36(9.8,-0.25) 37(9.8,0.25) 38(9.8,0.75) 39(9.8,1.25) 40(9.8,1.75) 41(9.8,2.25) 42(9.8,2.75) 43(9.8,3.25) 44(9.8,3.75) 45(9.8,4.25) 46(9.8,4.75) 47(9.8,5.25) 48(9.8,5.75)
Top Overlay:
  lines w0.12: -8.872,-6.02 8.875,-6.025 ; -8.872,6.02 8.875,6.015
  text "1" at -11.025,5.3 h1.5
M14-Top Assembly:
  circle w0.01: c-8.56,5.42 r0.391
  lines w0.01: -9.24,-5.875 -10.125,-5.875 -10.125,-5.625 -9.24,-5.625 ; -9.24,-5.375 -10.125,-5.375 -10.125,-5.125 -9.24,-5.125 ; -9.24,-4.875 -10.125,-4.875 -10.125,-4.625 -9.24,-4.625 ; -9.24,-4.375 -10.125,-4.375 -10.125,-4.125 -9.24,-4.125 ; -9.24,-3.875 -10.125,-3.875 -10.125,-3.625 -9.24,-3.625 ; -9.24,-3.375 -10.125,-3.375 -10.125,-3.125 -9.24,-3.125 ; -9.24,-2.875 -10.125,-2.875 -10.125,-2.625 -9.24,-2.625 ; -9.24,-2.375 -10.125,-2.375 -10.125,-2.125 -9.24,-2.125 ; -9.24,-1.875 -10.125,-1.875 -10.125,-1.625 -9.24,-1.625 ; -9.24,-1.375 -10.125,-1.375 -10.125,-1.125 -9.24,-1.125 ; -9.24,-0.875 -10.125,-0.875 -10.125,-0.625 -9.24,-0.625 ; -9.24,-0.375 -10.125,-0.375 -10.125,-0.125 -9.24,-0.125 ; -9.24,0.125 -10.125,0.125 -10.125,0.375 -9.24,0.375 ; -9.24,0.625 -10.125,0.625 -10.125,0.875 -9.24,0.875 ; -9.24,1.125 -10.125,1.125 -10.125,1.375 -9.24,1.375 ; -9.24,1.625 -10.125,1.625 -10.125,1.875 -9.24,1.875 ; -9.24,2.125 -10.125,2.125 -10.125,2.375 -9.24,2.375 ; -9.24,2.625 -10.125,2.625 -10.125,2.875 -9.24,2.875 ; -9.24,3.125 -10.125,3.125 -10.125,3.375 -9.24,3.375 ; -9.24,3.625 -10.125,3.625 -10.125,3.875 -9.24,3.875 ; -9.24,4.125 -10.125,4.125 -10.125,4.375 -9.24,4.375 ; -9.24,4.625 -10.125,4.625 -10.125,4.875 -9.24,4.875 ; -9.24,5.125 -10.125,5.125 -10.125,5.375 -9.24,5.375 ; -9.24,5.625 -10.125,5.625 -10.125,5.875 -9.24,5.875 ; 9.24,-5.875 10.125,-5.875 10.125,-5.625 9.24,-5.625 ; 9.24,-5.375 10.125,-5.375 10.125,-5.125 9.24,-5.125 ; 9.24,-4.875 10.125,-4.875 10.125,-4.625 9.24,-4.625 ; 9.24,-4.375 10.125,-4.375 10.125,-4.125 9.24,-4.125 ; 9.24,-3.875 10.125,-3.875 10.125,-3.625 9.24,-3.625 ; 9.24,-3.375 10.125,-3.375 10.125,-3.125 9.24,-3.125 ; 9.24,-2.875 10.125,-2.875 10.125,-2.625 9.24,-2.625 ; 9.24,-2.375 10.125,-2.375 10.125,-2.125 9.24,-2.125 ; 9.24,-1.875 10.125,-1.875 10.125,-1.625 9.24,-1.625 ; 9.24,-1.375 10.125,-1.375 10.125,-1.125 9.24,-1.125 ; 9.24,-0.875 10.125,-0.875 10.125,-0.625 9.24,-0.625 ; 9.24,-0.375 10.125,-0.375 10.125,-0.125 9.24,-0.125 ; 9.24,0.125 10.125,0.125 10.125,0.375 9.24,0.375 ; 9.24,0.625 10.125,0.625 10.125,0.875 9.24,0.875 ; 9.24,1.125 10.125,1.125 10.125,1.375 9.24,1.375 ; 9.24,1.625 10.125,1.625 10.125,1.875 9.24,1.875 ; 9.24,2.125 10.125,2.125 10.125,2.375 9.24,2.375 ; 9.24,2.625 10.125,2.625 10.125,2.875 9.24,2.875 ; 9.24,3.125 10.125,3.125 10.125,3.375 9.24,3.375 ; 9.24,3.625 10.125,3.625 10.125,3.875 9.24,3.875 ; 9.24,4.125 10.125,4.125 10.125,4.375 9.24,4.375 ; 9.24,4.625 10.125,4.625 10.125,4.875 9.24,4.875 ; 9.24,5.125 10.125,5.125 10.125,5.375 9.24,5.375 ; 9.24,5.625 10.125,5.625 10.125,5.875 9.24,5.875 ; -9.24,-6.02 9.24,-6.02 9.24,6.02 -9.24,6.02 -9.24,-6.02
  text "25" at 9.309,-6.025 h1
  text "48" at 9.309,5.45 h1
  text "1" at -9.94,5.475 h1
  text "24" at -10.171,-6.05 h1
  text "'.Designator'" at -2,-0.5 h0.75
M16-Top Courtyard:
  lines w0.01: -10.625,-6.275 -10.625,6.275 10.625,6.275 10.625,-6.275 -10.625,-6.275
3D body "User Library-TSOP48.STEP": height 1.2, standoff -0.06, extent -10.05,-6.05 10.05,6.05

## ICC_TSOP54_22P3X11P96_P080 [mm] "MCD-04265"
height 1.2
pads (54):
  rect 1.45x0.55 smd mask+0.05: 1(-5.5,10.4) 2(-5.5,9.6) 3(-5.5,8.8) 4(-5.5,8) 5(-5.5,7.2) 6(-5.5,6.4) 7(-5.5,5.6) 8(-5.5,4.8) 9(-5.5,4) 10(-5.5,3.2) 11(-5.5,2.4) 12(-5.5,1.6) 13(-5.5,0.8) 14(-5.5,0) 15(-5.5,-0.8) 16(-5.5,-1.6) 17(-5.5,-2.4) 18(-5.5,-3.2) 19(-5.5,-4) 20(-5.5,-4.8) 21(-5.5,-5.6) 22(-5.5,-6.4) 23(-5.5,-7.2) 24(-5.5,-8) 25(-5.5,-8.8) 26(-5.5,-9.6) 27(-5.5,-10.4) 28(5.5,-10.4) 29(5.5,-9.6) 30(5.5,-8.8) 31(5.5,-8) 32(5.5,-7.2) 33(5.5,-6.4) 34(5.5,-5.6) 35(5.5,-4.8) 36(5.5,-4) 37(5.5,-3.2) 38(5.5,-2.4) 39(5.5,-1.6) 40(5.5,-0.8) 41(5.5,0) 42(5.5,0.8) 43(5.5,1.6) 44(5.5,2.4) 45(5.5,3.2) 46(5.5,4) 47(5.5,4.8) 48(5.5,5.6) 49(5.5,6.4) 50(5.5,7.2) 51(5.5,8) 52(5.5,8.8) 53(5.5,9.6) 54(5.5,10.4)
Top Overlay:
  lines w0.12: -5.12,-10.875 -5.12,-11.15 5.12,-11.15 5.12,-10.875 ; -5.12,10.875 -5.12,11.15 5.12,11.15 5.12,10.875
  text "1" at -6.275,11.2 h1.5
M14-Top Assembly:
  drawing of 167 lines, arcs and shapes, not listed
  text "'.Designator'" at -2,-0.5 h0.75
M16-Top Courtyard:
  lines w0.01: -6.375,-11.4 -6.375,11.4 6.375,11.4 6.375,-11.4 -6.375,-11.4
3D body "ICC_TSOP54_22P3X11P96_P080-.step": height 1.2, standoff 0, extent -5.88,-11.15 5.88,11.15

## ICC_TSOP65P640X110_HS-17N [mm] "MCD-01593"
height 1.1
pads (17):
  rect 1.15x0.45 smd mask+0.05: 1(-2.775,2.275) 2(-2.775,1.625) 3(-2.775,0.975) 4(-2.775,0.325) 5(-2.775,-0.325) 6(-2.775,-0.975) 7(-2.775,-1.625) 8(-2.775,-2.275) 9(2.775,-2.275) 10(2.775,-1.625) 11(2.775,-0.975) 12(2.775,-0.325) 13(2.775,0.325) 14(2.775,0.975) 15(2.775,1.625) 16(2.775,2.275)
  rect 2.95x3.6 smd paste+0 mask+0.05: 17(0,0)
via -1.1,1.1 diameter 0.6 hole 0.2
via 0,1.1 diameter 0.6 hole 0.2
via 1.1,1.1 diameter 0.6 hole 0.2
via -1.1,0 diameter 0.6 hole 0.2
via 0,0 diameter 0.6 hole 0.2
via 1.1,0 diameter 0.6 hole 0.2
via -1.1,-1.1 diameter 0.6 hole 0.2
via 0,-1.1 diameter 0.6 hole 0.2
via 1.1,-1.1 diameter 0.6 hole 0.2
Top Overlay:
  circle w0.12: c-1.775,2.075 r0.206
  lines w0.12: -1.85,-2.5 1.85,-2.5 ; -1.85,2.5 1.85,2.5
  text "1" at -3.325,2.95 h1.5
Top Paste:
  rectangle: -1.47,-1.79 1.47,1.79
M14-Top Assembly:
  lines w0.01: -2.2,-2.5 -2.2,2.5 2.2,2.5 2.2,-2.5 -2.2,-2.5
  text ".Designator" at -3.3,-0.4 h1.5
M16-Top Courtyard:
  lines w0.01: -3.5,-2.7 -3.5,2.7 3.5,2.7 3.5,-2.7 -3.5,-2.7
3D body "TSOP65P640X110_HS-17N.step": height 1.1, standoff 0, extent -3.2,-2.55 3.2,2.55

## ICC_TSOT23-5L [mm] "MCD-04374"
height 1
pads (5):
  rect 0.6x1.2 smd mask+0.05: 1(-0.95,-1.3) 2(0,-1.3) 3(0.95,-1.3) 4(0.95,1.3) 5(-0.95,1.3)
Top Overlay:
  lines w0.12: -1.45,-0.875 -1.45,0.875 ; -0.5,0.875 0.5,0.875 ; 1.45,-0.875 1.45,0.875
  text "1" at -1.725,-2.025 h1.5
M14-Top Assembly:
  circle w0.01: c-1.125,-0.575 r0.224
  lines w0.01: -1.175,-0.875 -1.175,-1.4 -0.725,-1.4 -0.725,-0.875 ; -1.175,0.875 -1.175,1.4 -0.725,1.4 -0.725,0.875 ; -0.225,-0.875 -0.225,-1.4 0.225,-1.4 0.225,-0.875 ; 0.725,-0.875 0.725,-1.4 1.175,-1.4 1.175,-0.875 ; 0.725,0.875 0.725,1.4 1.175,1.4 1.175,0.875 ; -1.45,-0.875 1.45,-0.875 1.45,0.875 -1.45,0.875 -1.45,-0.875
  text "'.Designator'" at -2,-0.5 h0.75
  text "4" at 0.78,0.91 h0.75
  text "5" at -1.1,0.925 h0.75
  text "1" at -1.05,-1.425 h0.75
  text "3" at 0.78,-1.43 h0.75
  text "2" at -0.15,-1.425 h0.75
M16-Top Courtyard:
  lines w0.01: -1.7,-2.05 1.7,-2.05 1.7,2.05 -1.7,2.05 -1.7,-2.05
3D body "User Library-tsot-23-5.STEP": height 0.95, standoff -0.03, extent -1.45,-1.399 1.45,1.399

## ICC_TSOT23-6L [mm] "MCD-02681"
height 1
pads (6):
  rect 0.6x1.2 smd mask+0.05: 1(-0.95,-1.15) 2(0,-1.15) 3(0.95,-1.15) 4(0.95,1.15) 5(0,1.15) 6(-0.95,1.15)
Top Overlay:
  circle w0.12: c-1.225,-0.275 r0.141
  lines w0.12: -1.375,-0.875 -1.525,-0.875 -1.525,0.875 -1.375,0.875 ; 1.375,-0.875 1.525,-0.875 1.525,0.875 1.375,0.875 ; -1.675,-1.75 -1.525,-1.075 -1.375,-1.75 -1.675,-1.75
M14-Top Assembly:
  circle w0.01: c-1.25,-0.6 r0.224
  lines w0.01: -1.2,-0.875 -1.2,-1.5 -0.7,-1.5 -0.7,-0.875 ; -1.2,0.875 -1.2,1.5 -0.7,1.5 -0.7,0.875 ; -0.25,-0.875 -0.25,-1.5 0.25,-1.5 0.25,-0.875 ; -0.25,0.875 -0.25,1.5 0.25,1.5 0.25,0.875 ; 0.7,-0.875 0.7,-1.5 1.2,-1.5 1.2,-0.875 ; 0.7,0.875 0.7,1.5 1.2,1.5 1.2,0.875 ; -1.525,-0.875 -1.525,0.875 1.525,0.875 1.525,-0.875 -1.525,-0.875
  text "2" at -0.15,-1.425 h0.75
  text "3" at 0.78,-1.43 h0.75
  text "1" at -1.05,-1.425 h0.75
  text "6" at -1.1,0.925 h0.75
  text "5" at -0.15,0.925 h0.75
  text "4" at 0.78,0.91 h0.75
  text "'.Designator'" at 0,0 h0.75
M16-Top Courtyard:
  lines w0.01: -1.725,-1.9 -1.725,1.9 1.725,1.9 1.725,-1.9 -1.725,-1.9
3D body "User Library-TSOT-23.STEP": height 0.86, standoff 0, extent -1.5,-1.405 1.5,1.405

## ICC_TSOT23-8L [mm]
height 1
pads (8):
  rect 0.45x1 smd mask+0.05: 1(-0.975,-1.25) 2(-0.325,-1.25) 3(0.325,-1.25) 4(0.975,-1.25) 5(0.975,1.25) 6(0.325,1.25) 7(-0.325,1.25) 8(-0.975,1.25)
Top Overlay:
  circle w0.12: c-1.225,-0.275 r0.141
  lines w0.12: -1.375,-0.875 -1.525,-0.875 -1.525,0.875 -1.375,0.875 ; 1.375,-0.875 1.525,-0.875 1.525,0.875 1.375,0.875 ; -1.675,-1.75 -1.525,-1.075 -1.375,-1.75 -1.675,-1.75
M14-Top Assembly:
  circle w0.01: c-1.25,-0.6 r0.224
  lines w0.01: -1.155,-0.875 -1.155,-1.5 -0.795,-1.5 -0.795,-0.875 ; -1.155,0.875 -1.155,1.5 -0.795,1.5 -0.795,0.875 ; -0.505,-0.875 -0.505,-1.5 -0.145,-1.5 -0.145,-0.875 ; -0.505,0.875 -0.505,1.5 -0.145,1.5 -0.145,0.875 ; 0.145,-0.875 0.145,-1.5 0.505,-1.5 0.505,-0.875 ; 0.145,0.875 0.145,1.5 0.505,1.5 0.505,0.875 ; 0.795,-0.875 0.795,-1.5 1.155,-1.5 1.155,-0.875 ; 0.795,0.875 0.795,1.5 1.155,1.5 1.155,0.875 ; -1.525,-0.875 -1.525,0.875 1.525,0.875 1.525,-0.875 -1.525,-0.875
  text "1" at -1.075,-1.425 h0.75
  text "'.Designator'" at -2,-0.5 h0.75
M16-Top Courtyard:
  lines w0.01: -1.725,-1.9 -1.725,1.9 1.725,1.9 1.725,-1.9 -1.725,-1.9
3D body "User Library-SOT-23-8 Thin.STEP": height 1.1, standoff 0, extent -1.45,-1.48 1.45,1.478

## ICC_TSSOP5_SOT353-1_2P05X1P25_P065 [mm] "MCD-01960"
height 1.1
pads (5):
  rect 0.45x0.9 smd mask+0.05: 1(-0.65,-0.875) 2(0,-0.875) 3(0.65,-0.875) 4(0.65,0.875) 5(-0.65,0.875)
Top Overlay:
  lines w0.12: -1.087,-1.25 -1.087,-0.875 ; -1,-0.675 -1.125,-0.675 -1.125,0.675 -1,0.675 ; -0.3,0.675 0.3,0.675 ; 1,-0.675 1.125,-0.675 1.125,0.675 1,0.675 ; -1.175,-1.25 -1.175,-0.875 -1,-0.875 -1,-1.25 -1.175,-1.25
M14-Top Assembly:
  circle w0.01: c-0.775,-0.325 r0.2
  lines w0.01: -0.775,-0.675 -0.775,-1.125 -0.525,-1.125 -0.525,-0.675 ; -0.775,0.675 -0.775,1.125 -0.525,1.125 -0.525,0.675 ; -0.125,-0.675 -0.125,-1.125 0.125,-1.125 0.125,-0.675 ; 0.525,-0.675 0.525,-1.125 0.775,-1.125 0.775,-0.675 ; 0.525,0.675 0.525,1.125 0.775,1.125 0.775,0.675 ; -1.125,-0.675 -1.075,-0.625 ; -1.125,-0.675 -1.125,0.675 ; -1.125,-0.675 1.125,-0.675 ; -1.125,0.675 -1.075,0.625 ; -1.125,0.675 1.125,0.675 ; -1.075,-0.625 1.075,-0.625 ; -1.075,-0.625 -1.075,0.625 ; -1.075,0.625 1.075,0.625 ; 1.075,-0.625 1.125,-0.675 ; 1.075,-0.625 1.075,0.625 ; 1.075,0.625 1.125,0.675 ; 1.125,-0.675 1.125,0.675
  text "5" at -0.75,0.75 h0.5
  text "4" at 0.55,0.75 h0.5
  text "3" at 0.55,-1.05 h0.5
  text "2" at -0.1,-1.05 h0.5
  text "1" at -0.7,-1.05 h0.5
  text "'.Designator'" at -2,-0.5 h0.75
M16-Top Courtyard:
  lines w0.01: -1.325,-1.475 1.325,-1.475 1.325,1.475 -1.325,1.475 -1.325,-1.475
3D body: height 1.1, standoff 0, extent -1.235,-0.81 1.235,0.81
3D body "SOT353-1.STEP": height 1.1, standoff 0, extent -1.1,-1.2 1.1,1.2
